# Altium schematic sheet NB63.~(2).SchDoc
size 279 x 215 mm
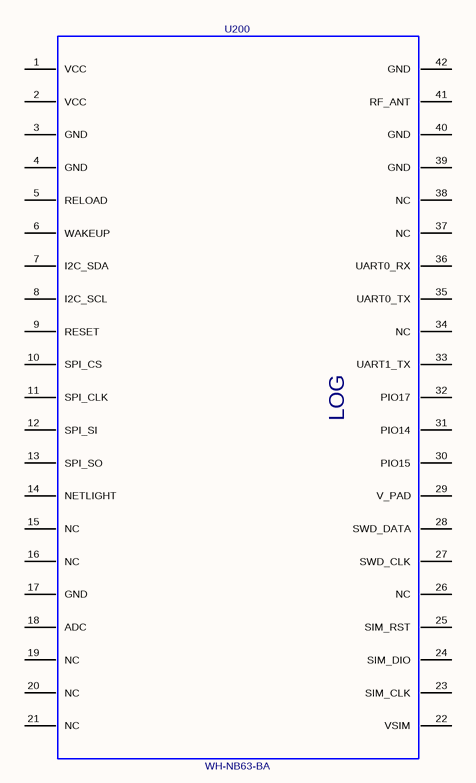
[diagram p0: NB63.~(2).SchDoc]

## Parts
U200  WH-NB63-BA  [NB63-I/O]

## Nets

Not connected (* = marked no-connect by the designer): U200 1(VCC) 2(VCC) 3(GND) 4(GND) 5(RELOAD) 6(WAKEUP) 7(I2C_SDA) 8(I2C_SCL) 9(RESET) 10(SPI_CS) 11(SPI_CLK) 12(SPI_SI) 13(SPI_SO) 14(NETLIGHT) 15(NC) 16(NC) 17(GND) 18(ADC) 19(NC) 20(NC) 21(NC) 22(VSIM) 23(SIM_CLK) 24(SIM_DIO) 25(SIM_RST) 26(NC) 27(SWD_CLK) 28(SWD_DATA) 29(V_PAD) 30(PIO15) 31(PIO14) 32(PIO17) 33(UART1_TX) 34(NC) 35(UART0_TX) 36(UART0_RX) 37(NC) 38(NC) 39(GND) 40(GND) 41(RF_ANT) 42(GND)

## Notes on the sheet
- (near U200) LOG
